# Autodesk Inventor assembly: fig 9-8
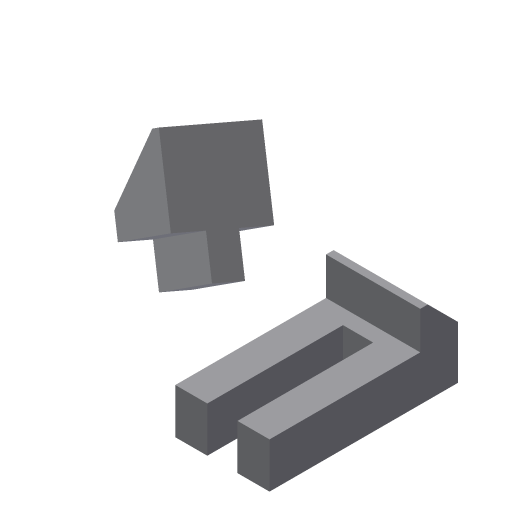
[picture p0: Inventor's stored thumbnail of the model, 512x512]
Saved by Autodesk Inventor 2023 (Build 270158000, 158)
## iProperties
Created: 2002-01
Part Number: fig 9-8
Document SubType Name: Assembly
Designer: ***
Control State: 0
Master: False
Checked Out: False
Shininess: 64.0
Length Units: 11269
Angle Units: 11279
Time Units: 11290
Mass Units: 11283
Length Display Precision: 3
Angle Display Precision: 2
Density: 0.0
Volumn: 0.0
Area: 0.0
PropertySet Name: Model Information
Author: ***
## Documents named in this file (3)
- D:\PROJECTS\Project 2022\Autodesk Inventor For Professional 2023\RESOURCES INVENTOR 2023\RESOURCES INVENTOR 2023\Inventor_2023_Part\Inventor_2023_Part\c09_Inv_2023_prt\fig 9-8.iam
- D:\PROJECTS\Project 2022\Autodesk Inventor For Professional 2023\RESOURCES INVENTOR 2023\RESOURCES INVENTOR 2023\Inventor_2023_Part\Inventor_2023_Part\c09_Inv_2023_prt\Part3.ipt
- D:\PROJECTS\Project 2022\Autodesk Inventor For Professional 2023\RESOURCES INVENTOR 2023\RESOURCES INVENTOR 2023\Inventor_2023_Part\Inventor_2023_Part\c09_Inv_2023_prt\Part4.ipt
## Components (2 placed, 2 different names)
1. Part3:1
2. Part4:1
